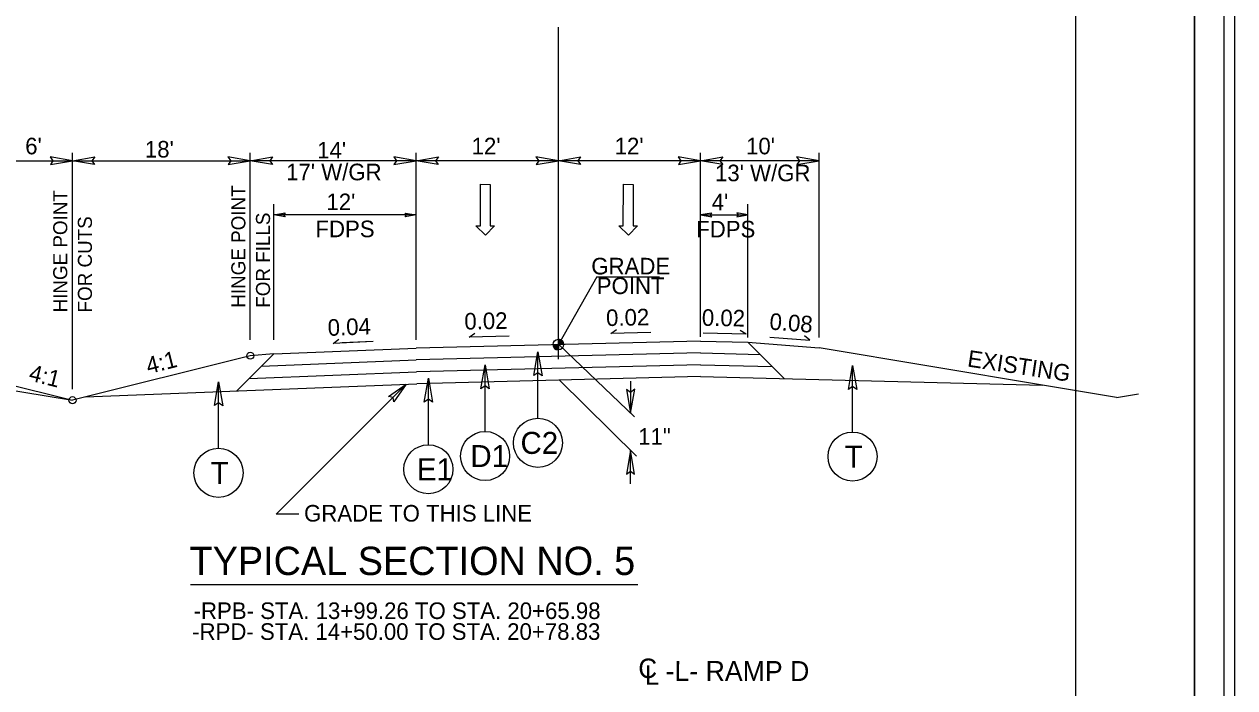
# Model space of a CAD drawing. Extents: x 1640342 to 1730599, y 538663 to 843747.
# Drawn here: x 1730075.2 to 1730177.4, y 539474.7 to 539530.7 of the extents above; entities that cross this region are included whole.
import ezdxf

# ---------------------------------------------------------------- set-up
doc = ezdxf.new("R2010")
doc.units = 0
for name, color, linetype in [('Default', 7, 'Continuous'), ('Prop Dimension Text', 7, 'Continuous'), ('Prop Terminator CELL', 7, 'Continuous'), ('Sheet Clip Boundary CELL', 7, 'Continuous'), ('Sheet Layout Plan Border', 7, 'Continuous'), ('Sheet Plan CELL', 7, 'Continuous'), ('Sheet Plan Layout CELL', 7, 'Continuous'), ('Sheet Plot Border Inside CELL', 7, 'Continuous'), ('Sheet Plot Border Outside CELL', 7, 'Continuous'), ('Typical Grade Point Symbol CELL', 7, 'Continuous'), ('Typical Hinge Slope Arterial CELL', 7, 'Continuous'), ('Typical ID Circle CELL', 7, 'Continuous'), ('Typical Pavement Slope CELL', 7, 'Continuous'), ('Typical Pavement Slope Information CELL', 7, 'Continuous'), ('Typical Terminator CELL', 7, 'Continuous'), ('Typical Text Centerline CELL', 7, 'Continuous'), ('Typical Text General CELL', 7, 'Continuous'), ('Typical Text Grade Point CELL', 7, 'Continuous'), ('Typical Text ID Circle CELL', 7, 'Continuous'), ('Typical Text Label CELL', 7, 'Continuous')]:
    doc.layers.add(name, color=color, linetype=linetype)

msp = doc.modelspace()

# ---------------------------------------------------------------- linework, layer by layer
at = {"layer": 'Default'}
for p, q in [((1730079.31, 539499.88), (1730079.31, 539519.8)), ((1730094.31, 539504.04), (1730094.31, 539519.8)), ((1730108.31, 539504.04), (1730108.31, 539519.8)), ((1730132.31, 539504.28), (1730132.31, 539519.8)), ((1730142.31, 539504.23), (1730142.31, 539519.8)), ((1730073.31, 539519.13), (1730079.31, 539519.13)), ((1730079.31, 539519.13), (1730094.31, 539519.13)), ((1730108.31, 539519.13), (1730094.31, 539519.13)), ((1730132.31, 539519.13), (1730108.31, 539519.13)), ((1730142.31, 539519.13), (1730132.31, 539519.13)), ((1730096.31, 539504.04), (1730096.31, 539515.49)), ((1730108.31, 539514.57), (1730096.31, 539514.57)), ((1730132.31, 539514.57), (1730136.31, 539514.57)), ((1730136.31, 539504.23), (1730136.31, 539515.49)), ((1730120.36, 539503.63), (1730126.73, 539497.53)), ((1730120.38, 539500.65), (1730126.91, 539494.21)), ((1730126.41, 539500.54), (1730126.41, 539497.84)), ((1730126.41, 539491.87), (1730126.41, 539494.7))]:
    msp.add_line(p, q, dxfattribs=at)
for points in [[(1730077.44, 539518.81), (1730079.31, 539519.13), (1730077.42, 539519.47), (1730077.66, 539519.13)], [(1730081.18, 539518.81), (1730079.31, 539519.13), (1730081.19, 539519.47), (1730080.95, 539519.13)], [(1730092.44, 539518.81), (1730094.31, 539519.13), (1730092.42, 539519.47), (1730092.66, 539519.13)], [(1730096.18, 539518.81), (1730094.31, 539519.13), (1730096.19, 539519.47), (1730095.95, 539519.13)], [(1730106.44, 539518.81), (1730108.31, 539519.13), (1730106.42, 539519.47), (1730106.66, 539519.13)], [(1730110.18, 539518.81), (1730108.31, 539519.13), (1730110.19, 539519.47), (1730109.95, 539519.13)], [(1730118.44, 539518.81), (1730120.31, 539519.13), (1730118.42, 539519.47), (1730118.66, 539519.13)], [(1730122.18, 539518.81), (1730120.31, 539519.13), (1730122.19, 539519.47), (1730121.95, 539519.13)], [(1730130.44, 539518.81), (1730132.31, 539519.13), (1730130.42, 539519.47), (1730130.66, 539519.13)], [(1730134.18, 539518.81), (1730132.31, 539519.13), (1730134.19, 539519.47), (1730133.95, 539519.13)], [(1730140.44, 539518.81), (1730142.31, 539519.13), (1730140.42, 539519.47), (1730140.66, 539519.13)], [(1730097.25, 539514.41), (1730096.31, 539514.57), (1730097.25, 539514.74), (1730097.13, 539514.57)], [(1730107.37, 539514.73), (1730108.31, 539514.57), (1730107.37, 539514.4), (1730107.49, 539514.57)], [(1730133.25, 539514.73), (1730132.31, 539514.57), (1730133.25, 539514.4), (1730133.13, 539514.57)], [(1730135.37, 539514.41), (1730136.31, 539514.57), (1730135.37, 539514.74), (1730135.49, 539514.57)]]:
    msp.add_lwpolyline(points, close=True, dxfattribs=at)
at = {"layer": 'Prop Terminator CELL'}
msp.add_lwpolyline([(1730105.99, 539499.24), (1730107.48, 539500.29), (1730106.43, 539498.79), (1730106.37, 539499.18)], close=True, dxfattribs=at)
at = {"layer": 'Sheet Clip Boundary CELL'}
msp.add_lwpolyline([(1729883.99, 539392.14), (1730163.99, 539392.14), (1730163.99, 539559.84), (1730126.14, 539559.84), (1730126.14, 539602.14), (1729883.99, 539602.14)], close=True, dxfattribs=at)
at = {"layer": 'Sheet Layout Plan Border'}
msp.add_lwpolyline([(1729883.99, 539392.14), (1730163.99, 539392.14), (1730163.99, 539559.84), (1730126.14, 539559.84), (1730126.14, 539602.14), (1729883.99, 539602.14)], close=True, dxfattribs=at)
at = {"layer": 'Sheet Plan CELL'}
for points in [[(1730174, 539602.14), (1729873.99, 539602.14), (1729873.99, 539392.14), (1730173.99, 539392.14)], [(1729873.99, 539392.14), (1729873.99, 539602.13), (1730133.98, 539602.14), (1730133.99, 539572.13), (1730173.99, 539572.13), (1730173.99, 539392.14)]]:
    msp.add_lwpolyline(points, close=True, dxfattribs=at)
at = {"layer": 'Sheet Plan Layout CELL'}
msp.add_lwpolyline([(1729873.99, 539602.13), (1729873.99, 539392.14), (1730173.99, 539392.14), (1730173.99, 539559.84), (1730126.14, 539559.84), (1730126.14, 539602.14)], close=True, dxfattribs=at)
at = {"layer": 'Sheet Plot Border Inside CELL'}
msp.add_lwpolyline([(1729843.29, 539391.64), (1730176.49, 539391.64), (1730176.49, 539602.64), (1729843.29, 539602.64)], close=True, dxfattribs=at)
at = {"layer": 'Sheet Plot Border Outside CELL'}
msp.add_lwpolyline([(1729840.69, 539387.64), (1730177.39, 539387.64), (1730177.39, 539606.64), (1729840.69, 539606.64)], close=True, dxfattribs=at)
at = {"layer": 'Typical Grade Point Symbol CELL'}
for p, q in [((1730119.86, 539503.63), (1730120.31, 539503.63)), ((1730120.31, 539503.63), (1730120.31, 539504.07)), ((1730120.76, 539503.63), (1730120.31, 539503.63)), ((1730120.31, 539503.18), (1730120.31, 539503.63)), ((1730120.31, 539503.63), (1730120.31, 539503.18))]:
    msp.add_line(p, q, dxfattribs=at)
for points in [[(1730119.86, 539503.63), (1730119.86, 539503.58)], [(1730119.87, 539503.63), (1730119.87, 539503.53)], [(1730119.88, 539503.63), (1730119.88, 539503.49)], [(1730119.89, 539503.63), (1730119.89, 539503.47)], [(1730119.9, 539503.63), (1730119.9, 539503.45)], [(1730119.91, 539503.63), (1730119.91, 539503.43)], [(1730119.92, 539503.63), (1730119.92, 539503.41)], [(1730119.93, 539503.63), (1730119.93, 539503.39)], [(1730119.94, 539503.63), (1730119.94, 539503.38)], [(1730119.94, 539503.63), (1730119.94, 539503.37)], [(1730119.95, 539503.63), (1730119.95, 539503.36)], [(1730119.96, 539503.63), (1730119.96, 539503.35)], [(1730119.97, 539503.63), (1730119.97, 539503.33)], [(1730119.98, 539503.63), (1730119.98, 539503.32)], [(1730119.99, 539503.63), (1730119.99, 539503.31)], [(1730120, 539503.63), (1730120, 539503.31)], [(1730120.01, 539503.63), (1730120.01, 539503.3)], [(1730120.02, 539503.63), (1730120.02, 539503.29)], [(1730120.03, 539503.63), (1730120.03, 539503.28)], [(1730120.03, 539503.63), (1730120.03, 539503.27)], [(1730120.04, 539503.63), (1730120.04, 539503.27)], [(1730120.05, 539503.63), (1730120.05, 539503.26)], [(1730120.06, 539503.63), (1730120.06, 539503.26)], [(1730120.07, 539503.63), (1730120.07, 539503.25)], [(1730120.08, 539503.63), (1730120.08, 539503.24)], [(1730120.09, 539503.63), (1730120.09, 539503.24)], [(1730120.1, 539503.63), (1730120.1, 539503.23)], [(1730120.11, 539503.63), (1730120.11, 539503.23)], [(1730120.11, 539503.63), (1730120.11, 539503.22)], [(1730120.12, 539503.63), (1730120.12, 539503.22)], [(1730120.13, 539503.63), (1730120.13, 539503.22)], [(1730120.14, 539503.63), (1730120.14, 539503.21)], [(1730120.15, 539503.63), (1730120.15, 539503.21)], [(1730120.16, 539503.63), (1730120.16, 539503.21)], [(1730120.17, 539503.63), (1730120.17, 539503.2)], [(1730120.18, 539503.63), (1730120.18, 539503.2)], [(1730120.19, 539503.63), (1730120.19, 539503.2)], [(1730120.2, 539503.63), (1730120.2, 539503.19)], [(1730120.2, 539503.63), (1730120.2, 539503.19)], [(1730120.21, 539503.63), (1730120.21, 539503.19)], [(1730120.22, 539503.63), (1730120.22, 539503.19)], [(1730120.23, 539503.63), (1730120.23, 539503.19)], [(1730120.24, 539503.63), (1730120.24, 539503.19)], [(1730120.25, 539503.63), (1730120.25, 539503.18)], [(1730120.26, 539503.63), (1730120.26, 539503.18)], [(1730120.27, 539503.63), (1730120.27, 539503.18)], [(1730120.28, 539503.63), (1730120.28, 539503.18)], [(1730120.28, 539503.63), (1730120.28, 539503.18)], [(1730120.29, 539503.63), (1730120.29, 539503.18)], [(1730120.3, 539503.63), (1730120.3, 539503.18), (1730120.3, 539503.18)], [(1730120.31, 539504.07), (1730120.31, 539504.07), (1730120.31, 539503.63)], [(1730120.32, 539504.07), (1730120.32, 539503.63)], [(1730120.33, 539504.07), (1730120.33, 539503.63)], [(1730120.34, 539504.07), (1730120.34, 539503.63)], [(1730120.35, 539504.07), (1730120.35, 539503.63)], [(1730120.36, 539504.07), (1730120.36, 539503.63)], [(1730120.37, 539504.07), (1730120.37, 539503.63)], [(1730120.38, 539504.07), (1730120.38, 539503.63)], [(1730120.39, 539504.07), (1730120.39, 539503.63)], [(1730120.39, 539504.07), (1730120.39, 539503.63)], [(1730120.4, 539504.06), (1730120.4, 539503.63)], [(1730120.41, 539504.06), (1730120.41, 539503.63)], [(1730120.42, 539504.06), (1730120.42, 539503.63)], [(1730120.43, 539504.06), (1730120.43, 539503.63)], [(1730120.44, 539504.06), (1730120.44, 539503.63)], [(1730120.45, 539504.05), (1730120.45, 539503.63)], [(1730120.46, 539504.05), (1730120.46, 539503.63)], [(1730120.47, 539504.05), (1730120.47, 539503.63)], [(1730120.47, 539504.04), (1730120.47, 539503.63)], [(1730120.48, 539504.04), (1730120.48, 539503.63)], [(1730120.49, 539504.03), (1730120.49, 539503.63)], [(1730120.5, 539504.03), (1730120.5, 539503.63)], [(1730120.51, 539504.03), (1730120.51, 539503.63)], [(1730120.52, 539504.02), (1730120.52, 539503.63)], [(1730120.53, 539504.02), (1730120.53, 539503.63)], [(1730120.54, 539504.01), (1730120.54, 539503.63)], [(1730120.55, 539504.01), (1730120.55, 539503.63)], [(1730120.55, 539504), (1730120.55, 539503.63)], [(1730120.56, 539504), (1730120.56, 539503.63)], [(1730120.57, 539503.99), (1730120.57, 539503.63)], [(1730120.58, 539503.98), (1730120.58, 539503.63)], [(1730120.59, 539503.98), (1730120.59, 539503.63)], [(1730120.6, 539503.97), (1730120.6, 539503.63)], [(1730120.61, 539503.96), (1730120.61, 539503.63)], [(1730120.62, 539503.95), (1730120.62, 539503.63)], [(1730120.63, 539503.94), (1730120.63, 539503.63)], [(1730120.64, 539503.93), (1730120.64, 539503.63)], [(1730120.64, 539503.92), (1730120.64, 539503.63)], [(1730120.65, 539503.91), (1730120.65, 539503.63)], [(1730120.66, 539503.9), (1730120.66, 539503.63)], [(1730120.67, 539503.89), (1730120.67, 539503.63)], [(1730120.68, 539503.88), (1730120.68, 539503.63)], [(1730120.69, 539503.86), (1730120.69, 539503.63)], [(1730120.7, 539503.85), (1730120.7, 539503.63)], [(1730120.71, 539503.83), (1730120.71, 539503.63)], [(1730120.72, 539503.81), (1730120.72, 539503.63)], [(1730120.72, 539503.79), (1730120.72, 539503.63)], [(1730120.73, 539503.77), (1730120.73, 539503.63)], [(1730120.74, 539503.74), (1730120.74, 539503.63)], [(1730120.75, 539503.69), (1730120.75, 539503.63)]]:
    msp.add_lwpolyline(points, dxfattribs=at)
msp.add_circle((1730120.31, 539503.63), 0.447, dxfattribs=at)
for start, end in [(179.9907, 269.9907), (359.9907, 89.9907)]:
    msp.add_arc((1730120.31, 539503.63), 0.447, start, end, dxfattribs=at)
at = {"layer": 'Typical Hinge Slope Arterial CELL'}
for p, q in [((1730094.31, 539502.69), (1730079.31, 539498.94)), ((1730096.31, 539502.85), (1730094.31, 539502.69)), ((1730063.31, 539501.6), (1730079.31, 539498.94)), ((1730073.31, 539500.44), (1730079.31, 539498.94))]:
    msp.add_line(p, q, dxfattribs=at)
for centre in [(1730094.31, 539502.69), (1730079.31, 539498.94)]:
    msp.add_circle(centre, 0.297, dxfattribs=at)
at = {"layer": 'Typical ID Circle CELL'}
for p, q in [((1730118.59, 539497.41), (1730118.59, 539503.02)), ((1730114.13, 539496.3), (1730114.13, 539501.91)), ((1730145.14, 539496.25), (1730145.14, 539501.86)), ((1730091.63, 539494.88), (1730091.63, 539500.49)), ((1730109.34, 539495.18), (1730109.34, 539500.79))]:
    msp.add_line(p, q, dxfattribs=at)
for centre in [(1730118.59, 539495.34), (1730114.13, 539494.23), (1730145.14, 539494.18), (1730109.34, 539493.11), (1730091.63, 539492.81)]:
    msp.add_circle(centre, 2.07, dxfattribs=at)
at = {"layer": 'Typical Pavement Slope CELL'}
for p, q in [((1730132.31, 539504.28), (1730132.31, 539519.5)), ((1730113.73, 539513.65), (1730113.73, 539517.15)), ((1730113.73, 539517.15), (1730114.56, 539517.14)), ((1730114.56, 539517.14), (1730114.56, 539513.64)), ((1730125.79, 539513.65), (1730125.8, 539517.15)), ((1730125.8, 539517.15), (1730126.62, 539517.14)), ((1730126.62, 539517.14), (1730126.62, 539513.64)), ((1730114.16, 539512.86), (1730113.36, 539513.65)), ((1730113.36, 539513.65), (1730113.73, 539513.65)), ((1730114.93, 539513.64), (1730114.16, 539512.86)), ((1730114.56, 539513.64), (1730114.93, 539513.64)), ((1730126.22, 539512.86), (1730125.42, 539513.65)), ((1730125.42, 539513.65), (1730125.79, 539513.65)), ((1730126.99, 539513.64), (1730126.22, 539512.86)), ((1730126.62, 539513.64), (1730126.99, 539513.64)), ((1730112.78, 539504.26), (1730113.26, 539504.6)), ((1730116.16, 539504.34), (1730112.78, 539504.26)), ((1730124.74, 539504.56), (1730125.22, 539504.9)), ((1730128.12, 539504.64), (1730124.74, 539504.56)), ((1730141.54, 539504), (1730141.07, 539504.37)), ((1730141.54, 539504), (1730141.07, 539504.37)), ((1730096.31, 539502.85), (1730108.31, 539503.33)), ((1730101.31, 539503.73), (1730101.79, 539504.08)), ((1730104.69, 539503.88), (1730101.31, 539503.73)), ((1730104.69, 539503.88), (1730102.07, 539503.77)), ((1730132.31, 539503.93), (1730108.31, 539503.33)), ((1730132.31, 539503.93), (1730136.31, 539503.83)), ((1730136.31, 539503.83), (1730142.31, 539503.35)), ((1730136.31, 539503.83), (1730139.39, 539500.75)), ((1730138.17, 539504.27), (1730140.78, 539504.06)), ((1730138.17, 539504.27), (1730141.54, 539504)), ((1730138.17, 539504.27), (1730140.78, 539504.06)), ((1730138.17, 539504.27), (1730141.54, 539504)), ((1730161.16, 539500.21), (1730142.31, 539503.35)), ((1730096.31, 539502.85), (1730093.18, 539499.72)), ((1730095.27, 539501.81), (1730108.31, 539502.33)), ((1730132.31, 539502.93), (1730108.31, 539502.33)), ((1730132.31, 539502.93), (1730137.34, 539502.8)), ((1730094.23, 539500.76), (1730108.34, 539501.33)), ((1730132.31, 539501.93), (1730108.34, 539501.33)), ((1730132.31, 539501.93), (1730138.36, 539501.78)), ((1730080.4, 539499.21), (1730108.38, 539500.33)), ((1730132.31, 539500.93), (1730108.38, 539500.33)), ((1730132.31, 539500.93), (1730161.16, 539500.21)), ((1730167.41, 539499.16), (1730161.16, 539500.21)), ((1730167.41, 539499.16), (1730169.26, 539499.47))]:
    msp.add_line(p, q, dxfattribs=at)
at = {"layer": 'Typical Pavement Slope Information CELL'}
for q in [(1730132.54, 539504.59), (1730132.54, 539504.59), (1730135.65, 539504.83), (1730135.65, 539504.83)]:
    msp.add_line((1730136.17, 539504.52), q, dxfattribs=at)
at = {"layer": 'Typical Terminator CELL'}
for p, q in [((1730096.51, 539489.33), (1730107.48, 539500.29)), ((1730098.42, 539489.33), (1730096.51, 539489.33))]:
    msp.add_line(p, q, dxfattribs=at)
for points in [[(1730118.25, 539501.01), (1730118.59, 539503.02), (1730118.95, 539501), (1730118.59, 539501.26)], [(1730113.78, 539499.9), (1730114.13, 539501.91), (1730114.48, 539499.89), (1730114.13, 539500.14)], [(1730144.79, 539499.85), (1730145.14, 539501.86), (1730145.5, 539499.84), (1730145.14, 539500.1)], [(1730091.29, 539498.48), (1730091.63, 539500.49), (1730091.99, 539498.47), (1730091.63, 539498.73)], [(1730108.99, 539498.78), (1730109.34, 539500.79), (1730109.7, 539498.77), (1730109.34, 539499.03)], [(1730126.06, 539499.85), (1730126.41, 539497.84), (1730126.76, 539499.86), (1730126.41, 539499.6)], [(1730126.75, 539492.7), (1730126.41, 539494.7), (1730126.05, 539492.69), (1730126.41, 539492.94)]]:
    msp.add_lwpolyline(points, close=True, dxfattribs=at)
at = {"layer": 'Typical Text Centerline CELL'}
msp.add_line((1730120.31, 539502.4), (1730120.31, 539530.4), dxfattribs=at)
at = {"layer": 'Typical Text Grade Point CELL'}
for q in [(1730120.31, 539503.63), (1730128.85, 539509.35)]:
    msp.add_line((1730123.55, 539509.35), q, dxfattribs=at)
at = {"layer": 'Typical Text Label CELL'}
msp.add_line((1730089.27, 539483.39), (1730127.01, 539483.39), dxfattribs=at)

# ---------------------------------------------------------------- texts
at = {"layer": 'Default'}
msp.add_text('11"', height=1.4, dxfattribs=at).set_placement((1730127.05, 539495.18))
at = {"layer": 'Prop Dimension Text'}
for s, p in [("6'", (1730075.32, 539519.68)), ("18'", (1730085.42, 539519.41)), ("10'", (1730136.15, 539519.68)), ("13' W/GR", (1730133.53, 539517.41)), ("12'", (1730100.74, 539514.97)), ('FDPS', (1730099.81, 539512.69))]:
    msp.add_text(s, height=1.4, dxfattribs=at).set_placement(p)
for s, p in [("14'", (1730099.96, 539519.33)), ("12'", (1730112.99, 539519.68)), ("12'", (1730125.06, 539519.68)), ("17' W/GR", (1730097.34, 539517.49)), ("4'", (1730133.25, 539514.95)), ('FDPS', (1730131.94, 539512.67))]:
    msp.add_text(s, height=1.4, rotation=360, dxfattribs=at).set_placement(p)
at = {"layer": 'Typical Hinge Slope Arterial CELL'}
for s, height, rotation, p in [('HINGE POINT ', 1.1873, 90, (1730078.87, 539506.34)), ('HINGE POINT ', 1.1873, 90, (1730093.9, 539506.74)), ('FOR FILLS', 1.187, 90, (1730095.98, 539506.74)), ('FOR CUTS', 1.187, 90, (1730080.95, 539506.34)), ('4:1', 1.4, 345.9638, (1730075.55, 539500.62))]:
    msp.add_text(s, height=height, rotation=rotation, dxfattribs=at).set_placement(p)
at = {"layer": 'Typical Pavement Slope CELL'}
for s, rotation, p in [('4:1', 14.0362, (1730085.72, 539501.14)), ('EXISTING', 351.4609, (1730154.77, 539501.79))]:
    msp.add_text(s, height=1.4, rotation=rotation, dxfattribs=at).set_placement(p)
at = {"layer": 'Typical Pavement Slope Information CELL'}
for s, rotation, p in [('0.02', 1.1457, (1730124.35, 539505.19)), ('0.02', 358.8543, (1730132.41, 539505.22)), ('0.02', 358.8543, (1730132.41, 539505.22)), ('0.04', 2.1043, (1730100.87, 539504.36)), ('0.02', 1.1457, (1730112.39, 539504.89)), ('0.08', 355.7124, (1730138.09, 539504.9)), ('0.08', 355.7124, (1730138.09, 539504.9))]:
    msp.add_text(s, height=1.4, rotation=rotation, dxfattribs=at).set_placement(p)
at = {"layer": 'Typical Text Centerline CELL'}
for s, height, rotation, p in [('C', 1.64, 0.0443, (1730127.06, 539475.5)), ('-L- RAMP D', 1.683, 359.9417, (1730129.36, 539475.26)), ('L', 1.64, 359.9912, (1730127.61, 539474.94))]:
    msp.add_text(s, height=height, rotation=rotation, dxfattribs=at).set_placement(p)
at = {"layer": 'Typical Text General CELL'}
msp.add_text('GRADE TO THIS LINE', height=1.4, dxfattribs=at).set_placement((1730098.85, 539488.7))
at = {"layer": 'Typical Text Grade Point CELL'}
for s, p in [('GRADE', (1730123.09, 539509.55)), ('POINT', (1730123.55, 539507.89))]:
    msp.add_text(s, height=1.4, rotation=359.9998, dxfattribs=at).set_placement(p)
at = {"layer": 'Typical Text ID Circle CELL'}
for s, height, p in [('C2', 1.854, (1730117.12, 539494.41)), ('D1', 1.854, (1730112.89, 539493.3)), ('T', 1.85, (1730144.48, 539493.25)), ('T', 1.85, (1730090.97, 539491.88)), ('E1', 1.854, (1730108.38, 539492.18))]:
    msp.add_text(s, height=height, dxfattribs=at).set_placement(p)
at = {"layer": 'Typical Text Label CELL'}
msp.add_text('TYPICAL SECTION NO. 5', height=2.3871, rotation=360, dxfattribs=at).set_placement((1730089.19, 539484.19))
for s, p in [('-RPB- STA. 13+99.26 TO STA. 20+65.98', (1730089.53, 539480.48)), ('-RPD- STA. 14+50.00 TO STA. 20+78.83', (1730089.41, 539478.72))]:
    msp.add_text(s, height=1.4, dxfattribs=at).set_placement(p)

doc.saveas('drawing.dxf')
